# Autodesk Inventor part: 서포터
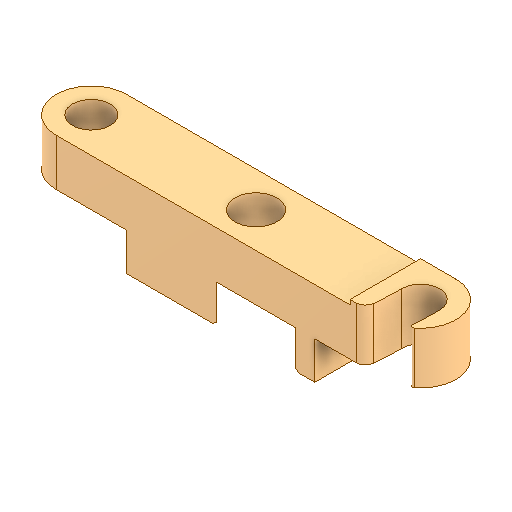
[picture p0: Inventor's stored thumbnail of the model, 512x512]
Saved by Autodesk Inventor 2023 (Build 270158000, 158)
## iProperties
Created: 2025-02
Part Number: 서포터
Material: 강철, 연강
Document SubType Name: Modeling
Designer: home
Density: 7.85 g/cm^3
Appearance: 기본값
Author: jhkim
Sending System: Autodesk Inventor 2025
Preprocessor: ST-DEVELOPER v20
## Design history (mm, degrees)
node "서포터1"
node "솔리드2"
node "솔리드1"
